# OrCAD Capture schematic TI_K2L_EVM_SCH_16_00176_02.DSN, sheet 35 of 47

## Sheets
35 PAGE43 : K2L_POWER SECTION 2: size C; title: Top Avatar, 12v to CVVD , 12v to 1.5v, 3.3v aux -> 1.2v, 3.3v aux -> 1.8v
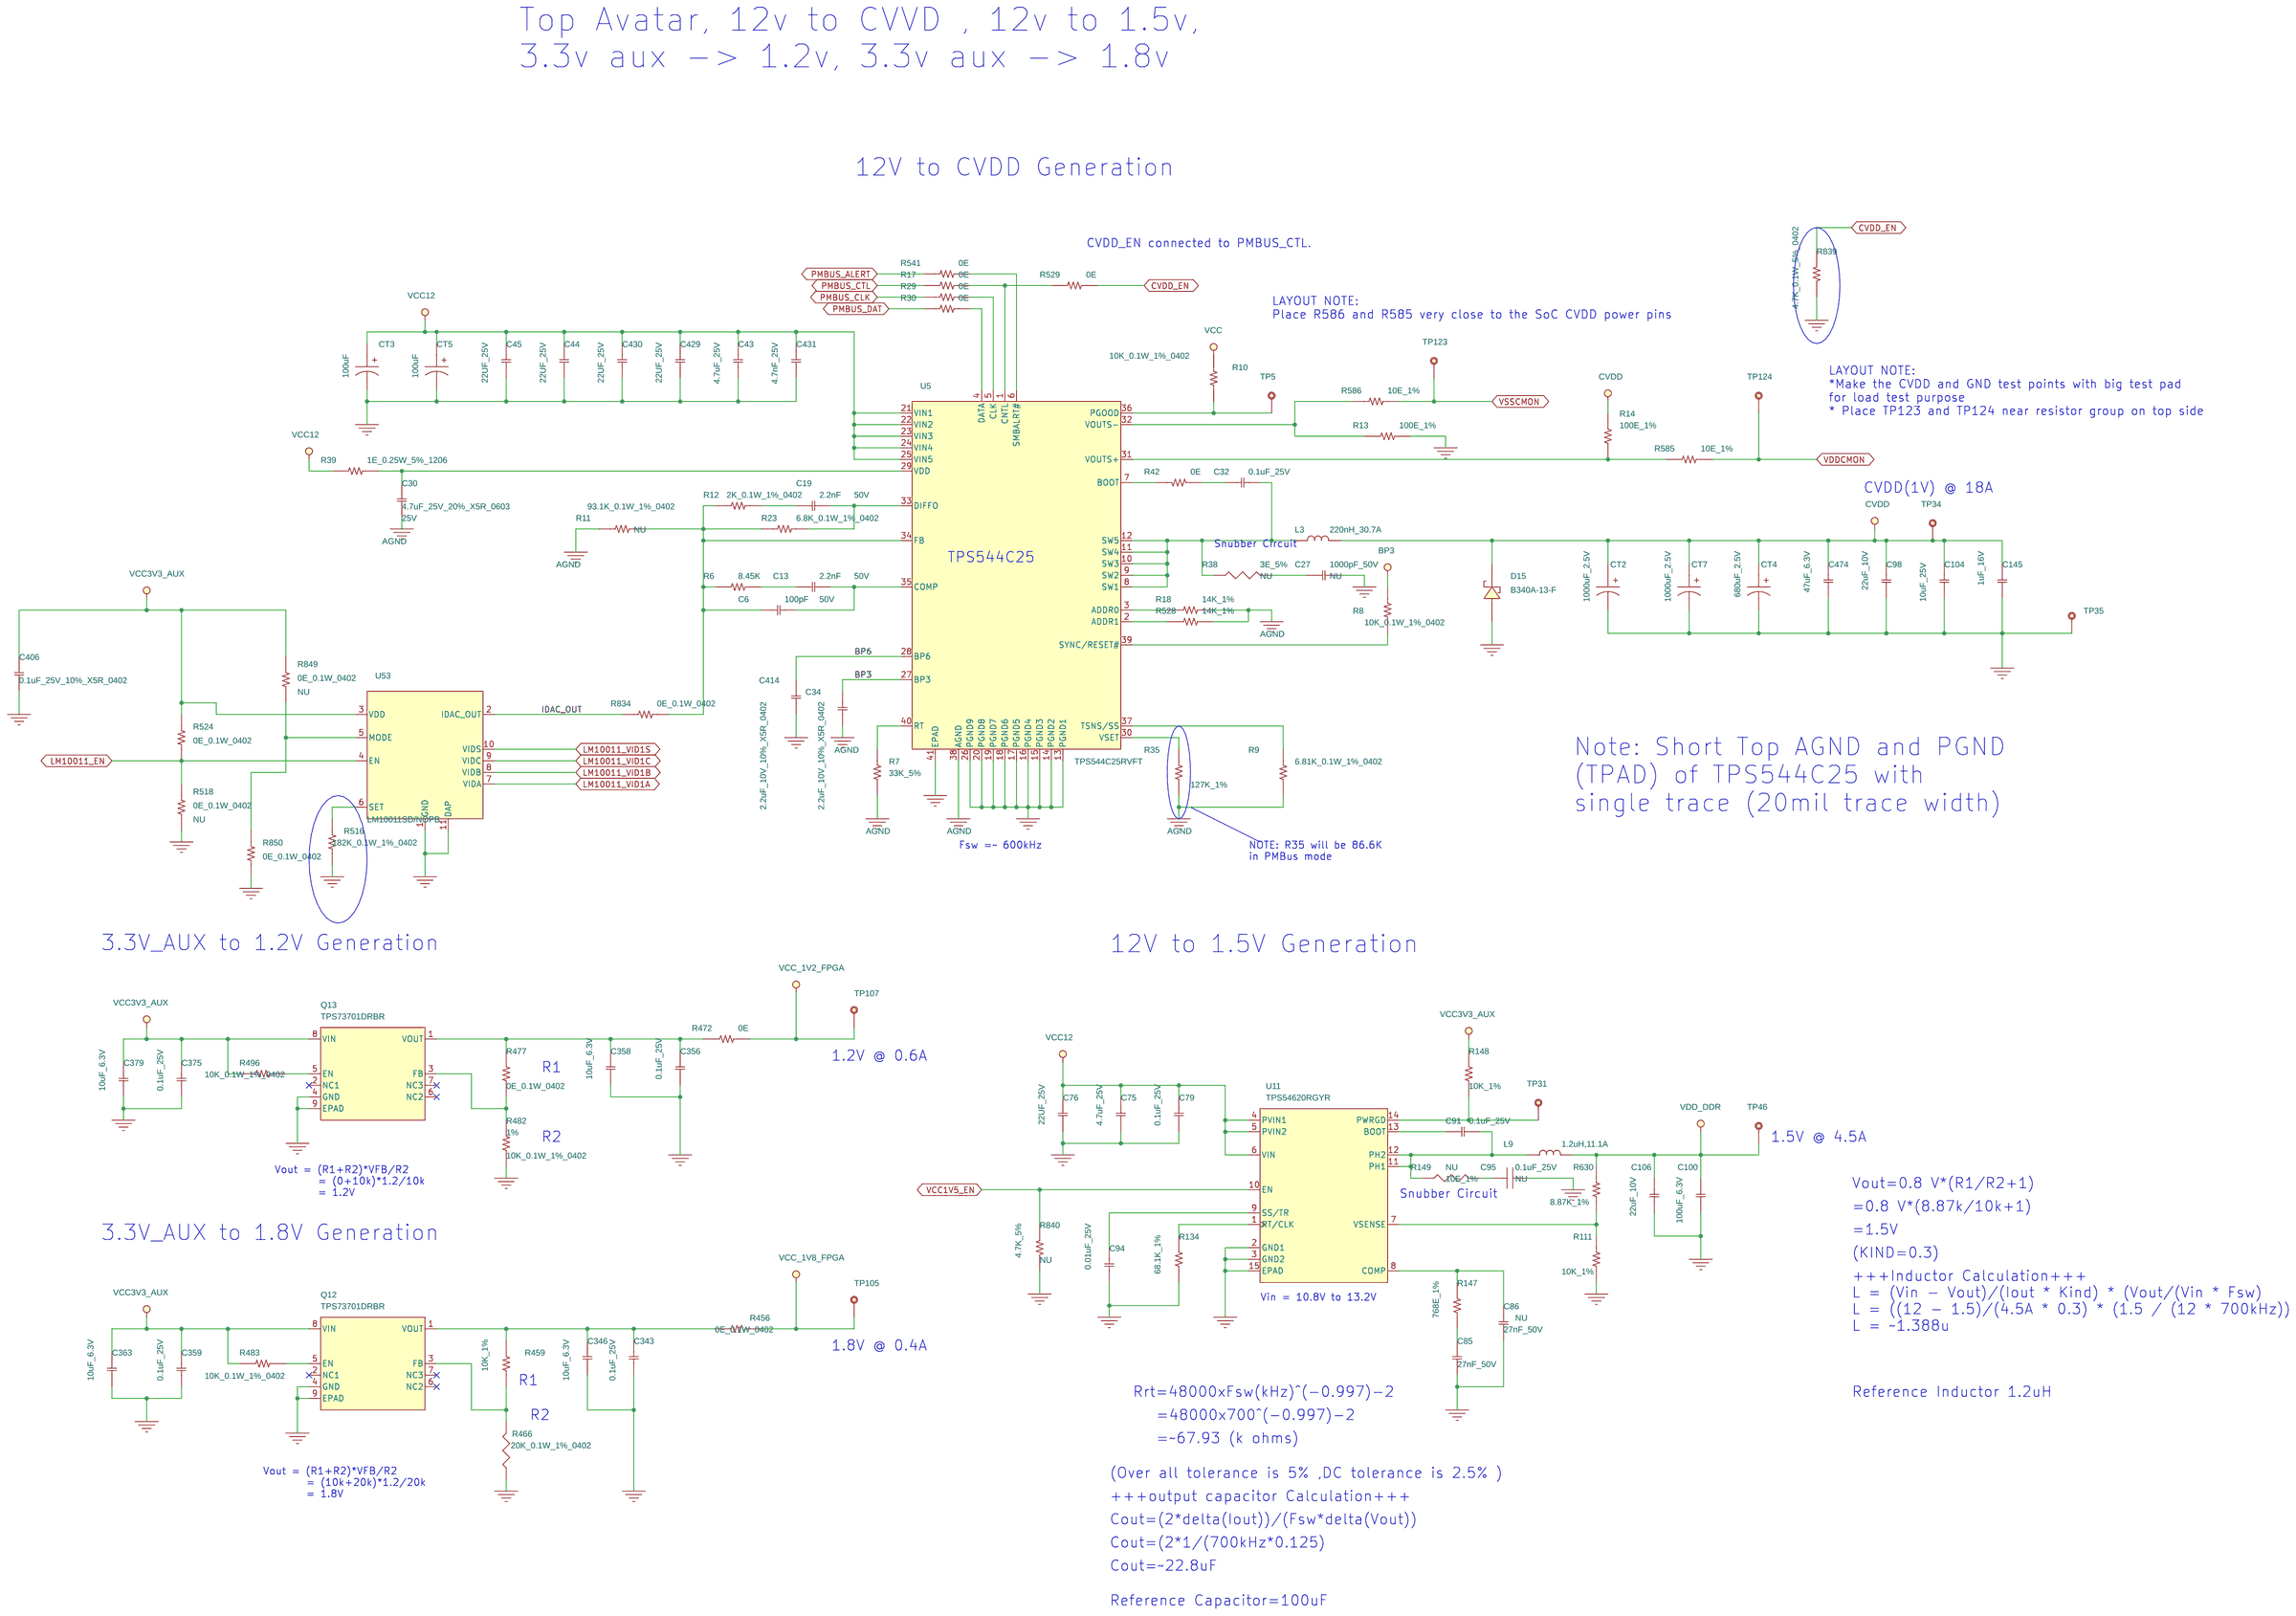
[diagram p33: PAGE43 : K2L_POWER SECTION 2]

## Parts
C6  100pF  [C0402]
C13  2.2nF  [C0402]
C19  2.2nF  [C0402]
C27  1000pF_50V  [C0402]
C30  4.7uF_25V_20%_X5R_0603  [C0603]
C32  0.1uF_25V  [C0402]
C34  2.2uF_10V_10%_X5R_0402  [C0402]
C43  4.7uF_25V  [C0603]
C44  22UF_25V  [C0805]
C45  22UF_25V  [C0805]
C75  4.7uF_25V  [C0603]
C76  22UF_25V  [C0805]
C79  0.1uF_25V  [C0402]
C85  27nF_50V  [C0805]
C86  27nF_50V  [C0805]
C91  0.1uF_25V  [C0402]
C94  0.01uF_25V  [C0402]
C95  0.1uF_25V  [C0402]
C98  22uF_10V  [C0805]
C100  100uF_6.3V  [C1206-1]
C104  10uF_25V  [C0603]
C106  22uF_10V  [C0805]
C145  1uF_16V  [C0402]
C343  0.1uF_25V  [C0402]
C346  10uF_6.3V  [C0603]
C356  0.1uF_25V  [C0402]
C358  10uF_6.3V  [C0603]
C359  0.1uF_25V  [C0402]
C363  10uF_6.3V  [C0603]
C375  0.1uF_25V  [C0402]
C379  10uF_6.3V  [C0603]
C406  0.1uF_25V_10%_X5R_0402  [C0402]
C414  2.2uF_10V_10%_X5R_0402  [C0402]
C429  22UF_25V  [C0805]
C430  22UF_25V  [C0805]
C431  4.7nF_25V  [CC0402]
C474  47uF_6.3V  [C0805]
CT2  1000uF_2.5V  [CT7343]
CT3  100uF  [CT7343]
CT4  680uF_2.5V  [CT7343]
CT5  100uF  [CT7343]
CT7  1000uF_2.5V  [CT7343]
D15  B340A-13-F  [DIODE_2P_158_197X110]
L3  220nH_30.7A  [IND_IHLP3232DZERR47M01]
L9  1.2uH,11.1A  [IND_XAL5030-222MEB]
Q12  TPS73701DRBR  [QFN_8P_26_118x118]
Q13  TPS73701DRBR  [QFN_8P_26_118x118]
R6  8.45K  [R0402]
R7  33K_5%  [R0402]
R8  10K_0.1W_1%_0402  [R0402]
R9  6.81K_0.1W_1%_0402  [R0402]
R10  10K_0.1W_1%_0402  [R0402]
R11  93.1K_0.1W_1%_0402  [R0402]
R12  2K_0.1W_1%_0402  [R0402]
R13  100E_1%  [R0402]
R14  100E_1%  [R0402]
R17  0E  [R0402]
R18  14K_1%  [R0402]
R23  6.8K_0.1W_1%_0402  [R0402]
R29  0E  [R0402]
R30  0E  [R0402]
R35  127K_1%  [R0402]
R38  3E_5%  [R0805]
R39  1E_0.25W_5%_1206  [R1206]
R42  0E  [R0402]
R111  10K_1%  [R0402]
R134  68.1K_1%  [R0603]
R147  768E_1%  [R0603]
R148  10K_1%  [R0402]
R149  10E_1%  [R0402]
R456  0E_0.1W_0402  [R0402]
R459  10K_1%  [R0402]
R466  20K_0.1W_1%_0402  [RC0402]
R472  0E  [R0402]
R477  0E_0.1W_0402  [R0402]
R482  10K_0.1W_1%_0402  [R0402]
R483  10K_0.1W_1%_0402  [R0402]
R496  10K_0.1W_1%_0402  [R0402]
R516  182K_0.1W_1%_0402  [R0402]
R518  0E_0.1W_0402  [R0402]
R524  0E_0.1W_0402  [R0402]
R528  14K_1%  [R0402]
R529  0E  [R0402]
R541  0E  [R0402]
R585  10E_1%  [R0402]
R586  10E_1%  [R0402]
R630  8.87K_1%  [R0402]
R834  0E_0.1W_0402  [R0402]
R839  4.7K_0.1W_5%_0402  [R0402]
R840  4.7K_5%  [R0402]
R849  0E_0.1W_0402  [R0402]
R850  0E_0.1W_0402  [R0402]
TP5  TP  [TP-S40]
TP31  TP  [TP-S40]
TP34  TP  [TP_71C]
TP35  TP  [TP_71C]
TP46  TP  [TP-S40]
TP105  TP  [TP-S40]
TP107  TP  [TP-S40]
TP123  TP  [TP-S40]
TP124  TP  [TP-S40]
U5  TPS544C25RVFT  [QFN50P500X700X152-41N]
U11  TPS54620RGYR  [QFN_14P_20_138x138_TP79]
U53  LM10011SD/NOPB  [WSON50P300X300X80-11N]

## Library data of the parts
C6 = Cap_Ceramic: CAP CER 100PF 50V 5% NP0 0402; Characteristic: <Characteristic>; Distributor_name: DIGIKEY; Distributor_part_number: 490-5922-1-ND; EIC Part#: 03_00594_01; Manufacture: Murata; Manufacture Part Number: GRM1555C1H101JA01D; Manufacture(English): 490-5922-1-ND; Manufacture_Part_Number: GRM1555C1H101JA01D; Manufacturer: Murata; Manufacturer_Part_No: GRM1555C1H101JA01D; Mfg: Murata; Mfg Part#: GRM1555C1H101JA01D; Mfr_name: Murata; Mfr_part_number: GRM1555C1H101JA01D; Oper. Temp. Range: -55°C ~ 125°C; Package: 0402; Price @ 1: 0.10000; Price @ 10K: 0.00500; Price @ 1K: 0.00600; ProcessType: SMT; RoHS: Yes; Tolerance: 5%; Vendor: DIGIKEY; Vendor Part#: 490-5922-1-ND; Vendor_Part_No: 490-5922-1-ND; Voltage: 50V; eI Part#: 03_00594_01
C13 C19 = Cap_Ceramic: CAP CER 2200PF 50V 10% X7R 0402; Distributor_name: Digikey; Distributor_part_number: 445-1257-1-ND; EIC Part#: TBD; Manufacture: TDK Corporation; Manufacture Part Number: C1005X7R1H222K050BA; Manufacture(English): TDK Corporation; Manufacture_Part_Number: C1005X7R1H222K050BA; Manufacturer: TDK Corporation; Manufacturer_Part_No: C1005X7R1H222K050BA; Mfg: TDK Corporation; Mfg Part#: C1005X7R1H222K050BA; Mfr_name: TDK Corporation; Mfr_part_number: C1005X7R1H222K050BA; Oper. Temp. Range: -55C to 85C; Package: 0402; ProcessType: SMT; RoHS: Yes; Tolerance: 10%; Vendor: DigiKey; Vendor Part#: 445-1257-6-ND; Voltage: 50V; eI Part#: TBD
C27 = 11_C_0: CAP CER 1000PF 50V 10% X7R 0402; Advansus_Part_Number: 11G232110214030; Distributor_name: DIGIKEY; Distributor_part_number: 1276-1493-1-ND; EIC Part#: 03_00591_01; Manufacture: Samsung; Manufacture Part Number: CL05B102KB5NFNC; Manufacture(English): Samsung; Manufacture_Part_Number: CL05B102KB5NFNC; Manufacturer: Samsung; Manufacturer_Part_No: CL05B102KB5NFNC; Mfg: Samsung; Mfg Part#: CL05B102KB5NFNC; Mfr_name: Samsung; Mfr_part_number: CL05B102KB5NFNC; Mounting: NU; Mounting Status: NU; Mounting_Status: NU; Oper. Temp. Range: -55C to 85C; Package: 0402; Price @ 1: 0.10000; Price @ 10K: 0.00260; Price @ 1K: 0.00372; ProcessType: SMT; RoHS: Yes; Tolerance: 10%; Vendor: DIGIKEY; Vendor Part#: 1276-1493-1-ND; Vendor_Part_No: 1276-1493-1-ND; Voltage: 50V; eI Part#: 03_00591_01
C30 C43 C75 = 11_C_0: CAP CER 4.7UF 25V 20% X5R 0603; Distributor_name: DIGIKEY; Distributor_part_number: 1276-1903-2-ND; EIC Part#: 03_00592_01; Manufacture: Samsung; Manufacture Part Number: CL10A475MA8NQNC; Manufacture(English): Samsung; Manufacture_Part_Number: CL10A475MA8NQNC; Manufacturer: Samsung; Manufacturer_Part_No: CL10A475MA8NQNC; Mfg: Samsung; Mfg Part#: CL10A475MA8NQNC; Mfr_name: Samsung; Mfr_part_number: CL10A475MA8NQNC; Oper. Temp. Range: -55C to 85C; Package: 0603; ProcessType: SMT; RoHS: Yes; Tolerance: 10%; Vendor: DIGIKEY; Vendor Part#: 1276-1903-2-ND; Vendor_Part_No: 1276-1903-2-ND; Voltage: 25V; eI Part#: 03_00592_01
C32 C79 C91 C406 = 11_C_0: CAP CER 0.1UF 25V 10% X5R 0402; Alt Mfg: Taiyo Yuden; Distributor_name: DIGIKEY; Distributor_part_number: 445-4964-1-ND; EIC Part#: 03_00470_02; Manufacture: TDK Corporation; Manufacture Part Number: C1005X5R1E104K050BC; Manufacture(English): TDK Corporation; Manufacture_Part_Number: GRM155R61E104KA87D; Manufacturer: TDK Corporation; Manufacturer_Part_No: C1005X5R1E104K050BC; Mfg: Murata Electronics North America; Mfg Part#: 03_00470_02; Mfr_name: TDK Corporation; Mfr_part_number: C1005X5R1E104K050BC; Oper. Temp. Range: -55°C ~ 85°C; Package: 0402; Price @ 1: 0.10000; Price @ 1K: 0.00960; ProcessType: SMT; RoHS: Yes; Tolerance: 10%; Vendor: DIGIKEY; Vendor Part#: 445-4964-1-ND; Vendor_Part_No: 445-4964-1-ND; eI Part#: 03_00470_02
C34 C414 = 11_C_12: CAP CER 2.2UF 10V 10% X5R 0402; Characteristic: <Characteristic>; Distributor_name: DIGIKEY; Distributor_part_number: 445-7392-1-ND; EIC Part#: 03_00055_05; Manufacture: TDK Corporation; Manufacture Part Number: C1005X5R1A225K050BC; Manufacture(English): TDK Corporation; Manufacture_Part_Number: C1005X5R1A225K050BC; Manufacturer: TDK Corporation; Manufacturer_Part_No: C1005X5R1A225K050BC; Mfg: TDK Corporation; Mfg Part#: C1005X5R1A225K050BC; Mfr_name: TDK Corporation; Mfr_part_number: C1005X5R1A225K050BC; Oper. Temp. Range: -55C to 105C; Package: 0402; Price @ 1: 0.32000; Price @ 10K: 0.06400; Price @ 1K: 0.09200; ProcessType: SMT; RoHS: Yes; Specifications: CAP CER 2.2UF 10V 10% X5R 0402; Tolerance: 10%; Vendor: DIGIKEY; Vendor Part#: 445-7392-1-ND; Vendor_Part_No: 445-7392-1-ND; Voltage: 6.3V; eI Part#: 03_00055_05
C44 C45 C76 C429 C430 = 11_C_0: CAP CER 22UF 25V 20% JB 0805; Alternate_Mfr: Samsung; Alternate_Partno: CL21A226MAQNNNE; Distributor_name: DIGIKEY; Distributor_part_number: 445-11475-2-ND; EIC Part#: 03_00586_01; Manufacture: TDK Corporation; Manufacture Part Number: C2012JB1E226M125AC; Manufacture(English): TDK Corporation; Manufacture_Part_Number: C2012JB1E226M125AC; Manufacturer: TDK Corporation; Manufacturer_Part_No: C2012JB1E226M125AC; Mfg: TDK Corporation; Mfg Part#: C2012JB1E226M125AC; Mfr_name: TDK Corporation; Mfr_part_number: C2012JB1E226M125AC; Oper. Temp. Range: -55C to 85C; Package: 0805; Price @ 1: 1.09000; Price @ 10K: 0.26265; Price @ 1K: 0.37647; ProcessType: SMT; RoHS: Yes; Tolerance: 10%; Vendor: DIGIKEY; Vendor Part#: 490-5527-1-ND; Vendor_Part_No: 03_00586_01; Voltage: 25V; eI Part#: 03_00586_01
C85 = 11_C_0: CAP CER 0.027UF 50V 10% X7R 0805; Distributor_name: DIGIKEY; Distributor_part_number: 311-1139-1-ND; EIC Part#: 03_00588_01; Manufacture: Yageo; Manufacture Part Number: CC0805KRX7R9BB273; Manufacture(English): Yageo; Manufacture_Part_Number: CC0805KRX7R9BB273; Manufacturer: Yageo; Manufacturer_Part_No: CC0805KRX7R9BB273; Mfg: Yageo; Mfg Part#: 03_00588_01; Mfr_name: Yageo; Mfr_part_number: CC0805KRX7R9BB273; Oper. Temp. Range: -55C ~ 125C; Package: 0805; Price @ 1: 0.10000; Price @ 10K: 0.01320; Price @ 1K: 0.01722; ProcessType: SMT; RoHS: Yes; Tolerance: 10%; Vendor: DIGIKEY; Vendor Part#: 311-1139-1-ND; Vendor_Part_No: 311-1139-1-ND; Voltage: 50V; eI Part#: 03_00588_01
C86 = 11_C_0: CAP CER 0.027UF 50V 10% X7R 0805; Distributor_name: DIGIKEY; Distributor_part_number: 311-1139-1-ND; EIC Part#: 03_00588_01; Manufacture: Yageo; Manufacture Part Number: CC0805KRX7R9BB273; Manufacture(English): Yageo; Manufacture_Part_Number: CC0805KRX7R9BB273; Manufacturer: Yageo; Manufacturer_Part_No: CC0805KRX7R9BB273; Mfg: Yageo; Mfg Part#: 03_00588_01; Mfr_name: Yageo; Mfr_part_number: CC0805KRX7R9BB273; Mounting: NU; Mounting Status: NU; Mounting_Status: NU; Oper. Temp. Range: -55C ~ 125C; Package: 0805; Price @ 1: 0.10000; Price @ 10K: 0.01320; Price @ 1K: 0.01722; ProcessType: SMT; RoHS: Yes; Tolerance: 10%; Vendor: DIGIKEY; Vendor Part#: 311-1139-1-ND; Vendor_Part_No: 311-1139-1-ND; Voltage: 50V; eI Part#: 03_00588_01
C94 = 11_C_0: CAP CER 10000PF 25V 10% X7R 0402; Alt Mfg: Murata; Alt Mfg Part#: GRM155R71C103KA01D; Distributor_name: DIGIKEY; Distributor_part_number: 445-1260-1-ND; EIC Part#: 03_00029_04; Manufacture: TDK Corporation; Manufacture Part Number: C1005X7R1E103K; Manufacture(English): TDK Corporation; Manufacture_Part_Number: C1005X7R1E103K; Manufacturer: TDK Corporation; Manufacturer_Part_No: C1005X7R1E103K; Mfg: TDK Corporation; Mfg Part#: 03_00029_04; Mfr_name: TDK Corporation; Mfr_part_number: C1005X7R1E103K; Oper. Temp. Range: -55C to 125C; Package: 0402; Price @ 1: 0.10000; Price @ 10K: 0.00420; Price @ 1K: 0.00600; ProcessType: SMT; RoHS: Yes; Tolerance: 10%; Vendor: DIGIKEY; Vendor Part#: PCC103BQCT-ND; Vendor_Part_No: 445-1260-1-ND; Voltage: 16V; eI Part#: 03_00029_04
C95 = CAP_NP: CAP CER 0.1UF 25V 10% X5R 0402; Alt Mfg: Taiyo Yuden; Distributor_name: DIGIKEY; Distributor_part_number: 445-4964-1-ND; EIC Part#: 03_00470_02; Manufacture: TDK Corporation; Manufacture Part Number: C1005X5R1E104K050BC; Manufacture(English): TDK Corporation; Manufacture_Part_Number: GRM155R61E104KA87D; Manufacturer: TDK Corporation; Manufacturer_Part_No: C1005X5R1E104K050BC; Mfg: Murata Electronics North America; Mfg Part#: 03_00470_02; Mfr_name: TDK Corporation; Mfr_part_number: C1005X5R1E104K050BC; Mounting: NU; Mounting Status: NU; Mounting_Status: NU; Oper. Temp. Range: -55°C ~ 85°C; Package: 0402; Price @ 1: 0.10000; Price @ 1K: 0.00960; RoHS: Yes; Vendor: DIGIKEY; Vendor Part#: 445-4964-1-ND; Vendor_Part_No: 445-4964-1-ND; eI Part#: 03_00470_02
C98 = Cap_Ceramic: CAP CER 22UF 10V 20% X5R 0805; Characteristic: <Characteristic>; Distributor_name: DIGIKEY; Distributor_part_number: 587-1958-1-ND; EIC Part#: 03_00263_01; Manufacture: Taiyo Yuden; Manufacture Part Number: LMK212BJ226MG-T; Manufacture(English): Taiyo Yuden; Manufacture_Part_Number: LMK212BJ226MG-T; Manufacturer: Taiyo Yuden; Manufacturer_Part_No: LMK212BJ226MG-T; Mfg: Taiyo Yuden; Mfg Part#: 03_00263_01; Mfr_name: Taiyo Yuden; Mfr_part_number: LMK212BJ226MG-T; Oper. Temp. Range: -55C to 85C; Package: 0805; Price @ 1: 0.53000; Price @ 10K: 0.12000; Price @ 1K: 0.16875; ProcessType: SMT; RoHS: Yes; Tolerance: 20%; Vendor: DIGIKEY; Vendor Part#: 587-1958-1-ND; Vendor_Part_No: 587-1958-1-ND; eI Part#: 03_00263_01
C100 = 11_C_0: CAP CER 100UF 6.3V 20% X5R 1206; Distributor_name: DIGIKEY; Distributor_part_number: 587-1453-1-ND; EIC Part#: 03_00380_04; Manufacture: Taiyo Yuden; Manufacture Part Number: JMK316BJ107ML-T; Manufacture(English): Taiyo Yuden; Manufacture_Part_Number: JMK316BJ107ML-T; Manufacturer: Taiyo Yuden; Manufacturer_Part_No: JMK316BJ107ML-T; Mfg: Taiyo Yuden; Mfg Part#: 03_00380_04; Mfr_name: Taiyo Yuden; Mfr_part_number: JMK316BJ107ML-T; Oper. Temp. Range: -55C to 85C; Package: 1206; Price @ 1: 1.80000; Price @ 10K: 0.30450; Price @ 1K: 0.43050; ProcessType: SMT; RoHS: Yes; Tolerance: 20%; Vendor: DIGIKEY; Vendor Part#: 587-1963-1-ND; Vendor_Part_No: 587-1453-1-ND; Voltage: 6.3V; eI Part#: 03_00380_04
C104 = Cap_Ceramic: CAP CER 10UF 25V 20% X5R 0603; Characteristic: <Characteristic>; Distributor_name: DIGIKEY; Distributor_part_number: 445-9015-1-ND; EIC Part#: 03_00609_01; Manufacture: TDK Corporation; Manufacture Part Number: C1608X5R1E106M080AC; Manufacture(English): TDK Corporation; Manufacture_Part_Number: C1608X5R1E106M080AC; Manufacturer: TDK Corporation; Manufacturer_Part_No: C1608X5R1E106M080AC; Mfg: TDK Corporation; Mfg Part#: C1608X5R1E106M080AC; Mfr_name: TDK Corporation; Mfr_part_number: C1608X5R1E106M080AC; Oper. Temp. Range: -55C to 85C; Package: 0603; ProcessType: SMT; RoHS: Yes; Tolerance: 20%; Vendor: DIGIKEY; Vendor Part#: TDK Corporation; Vendor_Part_No: 445-9015-1-ND; eI Part#: 03_00609_01
C106 = 11_C_0: CAP CER 22UF 10V 20% X5R 0805; Distributor_name: DIGIKEY; Distributor_part_number: 587-1958-1-ND; EIC Part#: 03_00263_01; Manufacture: Taiyo Yuden; Manufacture Part Number: LMK212BJ226MG-T; Manufacture(English): Taiyo Yuden; Manufacture_Part_Number: LMK212BJ226MG-T; Manufacturer: Taiyo Yuden; Manufacturer_Part_No: LMK212BJ226MG-T; Mfg: Taiyo Yuden; Mfg Part#: 03_00263_01; Mfr_name: Taiyo Yuden; Mfr_part_number: LMK212BJ226MG-T; Oper. Temp. Range: -55C to 85C; Package: 0805; Price @ 1: 0.53000; Price @ 10K: 0.12000; Price @ 1K: 0.16875; ProcessType: SMT; RoHS: Yes; Tolerance: 20%; Vendor: DIGIKEY; Vendor Part#: 587-1958-1-ND; Vendor_Part_No: 587-1958-1-ND; Voltage: 10V; eI Part#: 03_00263_01
C145 = Cap_Ceramic: CAP CER 1UF 16V 10% X5R 0402; Characteristic: <Characteristic>; Distributor_name: DIGIKEY; Distributor_part_number: 445-4978-1-ND; EIC Part#: 03_00355_04; Manufacture: TDK Corporation; Manufacture Part Number: C1005X5R1C105K050BC; Manufacture(English): TDK Corporation; Manufacture_Part_Number: C1005X5R1C105K050BC; Manufacturer: TDK Corporation; Manufacturer_Part_No: C1005X5R1C105K050BC; Mfg: TDK Corporation; Mfg Part#: C1005X5R1C105K050BC; Mfr_name: TDK Corporation; Mfr_part_number: C1005X5R1C105K050BC; Oper. Temp. Range: -55C to 85C; Package: 0402; ProcessType: SMT; RoHS: Yes; Tolerance: 10%; Vendor: DIGIKEY; Vendor Part#: 445-4978-1-ND; Vendor_Part_No: 445-4978-1-ND; eI Part#: 03_00355_04
C343 C356 C359 C375 = 11_C_0: CAP CER 0.1UF 25V 10% X5R 0402; Alt Mfg: Murata; Distributor_name: DIGIKEY; Distributor_part_number: 445-4964-1-ND; EIC Part#: 03_00470_02; Manufacture: TDK Corporation; Manufacture Part Number: C1005X5R1E104K050BC; Manufacture(English): TDK Corporation; Manufacture_Part_Number: GRM155R61E104KA87D; Manufacturer: TDK Corporation; Manufacturer_Part_No: C1005X5R1E104K050BC; Mfg: Murata Electronics North America; Mfg Part#: 03_00470_02; Mfr_name: TDK Corporation; Mfr_part_number: C1005X5R1E104K050BC; Oper. Temp. Range: -55C to 85C; Package: 0402; Price @ 1: 0.10000; Price @ 1K: 0.00960; ProcessType: SMT; RoHS: Yes; Tolerance: 10%; Vendor: DIGIKEY; Vendor Part#: 445-4964-1-ND; Vendor_Part_No: 445-4964-1-ND; eI Part#: 03_00470_02
C346 C358 C363 C379 = 11_C_0: CAP CER 10UF 6.3V 20% X5R 0603; Distributor_name: DIGIKEY; Distributor_part_number: 587-3383-1-ND; EIC Part#: 03_00605_01; Manufacture: Taiyo Yuden; Manufacture Part Number: JMK107ABJ106MAHT; Manufacture(English): Taiyo Yuden; Manufacture_Part_Number: JMK107ABJ106MAHT; Manufacturer: Taiyo Yuden; Manufacturer_Part_No: JMK107ABJ106MAHT; Mfg: Taiyo Yuden; Mfg Part#: JMK107ABJ106MAHT; Mfr_name: Taiyo Yuden; Mfr_part_number: JMK107ABJ106MAHT; Oper. Temp. Range: -55C to 85C; Package: 0603; Price @ 10K: 0.06105; ProcessType: SMT; RoHS: Yes; Tolerance: 20%; Vendor: DIGIKEY; Vendor Part#: 587-3383-1-ND; Vendor_Part_No: 587-3383-1-ND; eI Part#: 03_00605_01
C431 = 11_C_0: CAP CER 4700PF 25V 10% X7R 0402; Distributor_name: DIGIKEY; Distributor_part_number: 311-1039-1-ND; EIC Part#: 03_00338_03; Manufacture: Yageo; Manufacture Part Number: CC0402KRX7R8BB472; Manufacture(English): Yageo; Manufacture_Part_Number: CC0402KRX7R8BB472; Manufacturer: Yageo; Manufacturer_Part_No: CC0402KRX7R8BB472; Mfg: Yageo; Mfg Part#: 03_00338_03; Mfr_name: Yageo; Mfr_part_number: CC0402KRX7R8BB472; Oper. Temp. Range: -55C to 85C; Package: 0402; Price @ 1: 0.10000; Price @ 10K: 0.00216; Price @ 1K: 0.00309; ProcessType: SMT; RoHS: Yes; Tolerance: 10%; Vendor: DIGIKEY; Vendor Part#: 311-1039-1-ND; Vendor_Part_No: 311-1039-1-ND; Voltage: 25V; eI Part#: 03_00338_03
C474 = Cap_Ceramic: CAP CER 47UF 6.3V 20% X5R 0805; Distributor_name: DIGIKEY; Distributor_part_number: 587-1779-1-ND; EIC Part#: 03_00328_01; Manufacture: Taiyo Yuden; Manufacture Part Number: JMK212BJ476MG-T; Manufacture(English): Taiyo Yuden; Manufacturer: Taiyo Yuden; Manufacturer_Part_No: JMK212BJ476MG-T; Mfg: Taiyo Yuden; Mfg Part#: 03_00328_01; Mfr_name: Taiyo Yuden; Mfr_part_number: JMK212BJ476MG-T; Oper. Temp. Range: -55C to 105C; Package: 0805; ProcessType: SMT; RoHS: Yes; Tolerance: 20%; Vendor: DIGIKEY; Vendor Part#: 587-1779-1-ND; Vendor_Part_No: 587-1779-1-ND; eI Part#: 03_00328_01
CT2 CT7 = CAP_POL: CAP TANT 1000UF 2.5V 20% 2917; Distributor_name: DIGIKEY; Distributor_part_number: 399-4749-1-ND; EIC Part#: 03_00287_01; Manufacture: Kemet; Manufacture Part Number: T530Y108M2R5ATE005; Manufacture(English): Kemet; Manufacturer: Kemet; Manufacturer_Part_No: T530Y108M2R5ATE005; Mfg: Kemet; Mfg Part#: 03_00287_01; Mfr_name: Kemet; Mfr_part_number: T530Y108M2R5ATE005; Oper. Temp. Range: -55°C ~ 105°C; Package: 7343; RoHS: Yes; Vendor: DIGIKEY; Vendor Part#: 399-4749-2-ND; Vendor_Part_No: 399-4749-1-ND; eI Part#: 03_00287_01
CT3 CT5 = CAP_POL: CAP TANT 100UF 20V 10% 2917; Distributor_name: DIGIKEY; Distributor_part_number: 718-1774-1-ND; EIC Part#: 03_00602_01; Manufacture: Vishay; Manufacture Part Number: TR3D107K020C0080; Manufacture(English): Vishay Dale; Manufacture_Part_Number: TR3D107K020C0080; Manufacturer: Vishay Dale; Manufacturer_Part_No: TR3D107K020C0080; Mfg: Vishay Dale; Mfg Part#: TR3D107K020C0080; Mfr_name: Vishay Dale; Mfr_part_number: TR3D107K020C0080; Oper. Temp. Range: -40°C ~ 85°C; Package: 7343; RoHS: Yes; Vendor: DIGIKEY; Vendor Part#: 718-1774-1-ND; Vendor_Part_No: 718-1774-1-ND; Voltage: 25V; eI Part#: 03_00602_01
CT4 = CAP_POL: CAP TANT 680UF 2.5V 20% 2917; Distributor_name: DIGIKEY; Distributor_part_number: P16221CT-ND; EIC Part#: TBD; Manufacture: Panasonic - ECG; Manufacture Part Number: 2R5TPF680ML; Manufacture(English): Panasonic - ECG; Manufacturer: Panasonic - ECG; Manufacturer_Part_No: 2R5TPF680ML; Mfg: Panasonic - ECG; Mfg Part#: TBD; Mfr_name: Panasonic - ECG; Mfr_part_number: 2R5TPF680ML; Oper. Temp. Range: -55°C ~ 105°C; Package: 7343; RoHS: Yes; Vendor: DIGIKEY; Vendor Part#: P16221CT-ND; Vendor_Part_No: P16221CT-ND; eI Part#: TBD
D15 = Schottky_Diode: DIODE SCHOTTKY 3A 40V SMA; Distributor_name: DIGIKEY; Distributor_part_number: B340A-FDICT-ND; EIC Part#: 06_00002_01; Manufacture: Diodes Inc; Manufacture(English): Diodes Inc; Manufacturer: Diodes Inc; Mfg: Diodes Inc; Mfr_name: Diodes Inc; Oper. Temp. Range: -55C to 85C; Package: DO-214AC; RoHS: Yes; Vendor: DigiKey; Vendor Part#: B340A-FDICT-ND; Vendor_Part_No: B340A-FDICT-ND; eI Part#: 06_00002_01
L3 = 1211_CHOKE_0: INDUCTOR POWER .22UH 30.7A SMD; Distributor_name: DIGIKEY; Distributor_part_number: 541-1378-1-ND; EIC Part#: TBD; Manufacture: Vishay Dale; Manufacture Part Number: IHLP3232DZERR22M01; Manufacture(English): Vishay Dale; Manufacturer: Vishay Dale; Manufacturer_Part_No: IHLP3232DZERR22M01; Mfg: Coilcraft; Mfg Part#: TBD; Mfr_name: Vishay Dale; Mfr_part_number: IHLP3232DZERR22M01; ProcessType: SMT; RoHS: Yes; Vendor: DIGIKEY; Vendor Part#: 541-1378-1-ND; Vendor_Part_No: 541-1378-1-ND; eI Part#: TBD
L9 = 1211_CHOKE_0: INDUCTOR 1.2UH  20% SMD; Current: 2.3A Irms; Distributor_name: Mouser; Distributor_part_number: 994-XAL5030-122MEB; EIC Part#: 04_00410_01; Manufacture: Coilcraft Inc; Manufacture Part Number: XAL5030-122MEB; Manufacture(English): Coilcraft Inc; Manufacture_Part_Number: XAL5030-122MEB; Manufacturer: Coilcraft Inc; Manufacturer_Part_No: XAL5030-122MEB; Mfg Part#: 04_00410_01; Mfr_name: Coilcraft Inc; Mfr_part_number: XAL5030-122MEB; ProcessType: SMT; RoHS: Yes; Tolerance: 20%; Vendor: Mouser; Vendor Part#: XAL5030-122MEB; Vendor_Part_No: 994-XAL5030-122MEB; eI Part#: 04_00410_01
Q12 Q13 = TPS73701DRBT: IC REG LDO ADJ 1A 8SON; Distributor_name: DIGIKEY; Distributor_part_number: 296-22065-1-ND; EIC Part#: 01_00822_01; Manufacture: TI; Manufacture(English): TI; Manufacturer: TI; Mfg: TI; Mfg Part#: 01_00822_01; Mfr_name: TI; Oper. Temp. Range: -40°C ~ 125°C; Package: SON8; Price @ 1: 1.72000; Price @ 10K: 0.67500; Price @ 1K: 0.68851; ProcessType: SMT; RoHS: Yes; Vendor: DIGIKEY; Vendor Part#: 296-27067-1-ND; Vendor_Part_No: 296-22065-1-ND; eI Part#: 01_00822_01
R6 = 10_R_0: RES 8.45K OHM 1/16W 1% 0402 SMD; Distributor_name: Digikey; Distributor_part_number: 541-8.45KLCT-ND; EIC Part#: TBD; Manufacture: Vishay Dale; Manufacture Part Number: CRCW04028K45FKED; Manufacture(English): Vishay Dale; Manufacture_Part_Number: CRCW04028K45FKED; Manufacturer: Vishay Dale; Manufacturer_Part_No: CRCW04028K45FKED; Mfg: Vishay Dale; Mfg Part#: CRCW04028K45FKED; Mfr_name: Vishay Dale; Mfr_part_number: CRCW04028K45FKED; Oper. Temp. Range: -55C ~ 125C; Package: 0402; ProcessType: SMT; Remark: Alt part is 1/16W; RoHS: Yes; Tolerance: 1%; Vendor: DigiKey; Vendor Part#: 541-8.45KLCT-ND; eI Part#: TBD
R7 = 10_R_0: RES 33K OHM 1/10W 5% 0402 SMD; Distributor_name: DIGIKEY; Distributor_part_number: P33KJCT-ND; EIC Part#: 02_00356_01; Manufacture: Panasonic - ECG; Manufacture Part Number: ERJ-2GEJ333X; Manufacture(English): Panasonic - ECG; Manufacture_Part_Number: ERJ-2GEJ333X; Manufacturer: Panasonic - ECG; Manufacturer_Part_No: ERJ-2GEJ333X; Mfg Part#: 02_00356_01; Mfr_name: Panasonic - ECG; Mfr_part_number: ERJ-2GEJ333X; Oper. Temp. Range: -55C ~ 125C; Package: 0402; ProcessType: SMT; Remark: Alt part is 1/10W; RoHS: Yes; Tolerance: 5%; Vendor: DIGIKEY; Vendor Part#: P33KJCT-ND; Vendor_Part_No: P33KJCT-ND; eI Part#: 02_00483_01
R8 R10 R111 R148 R459 R482 R483 R496 = 10_R_0: RES 10K OHM 1/10W 1% 0402 SMD; Alt Mfg: Yageo; Alt Mfg Part#: RC0402FR-0710KL; Distributor_name: DIGIKEY; Distributor_part_number: P10.0KLCT-ND; EIC Part#: 02_00027_01; Manufacture: Panasonic - ECG; Manufacture Part Number: ERJ-2RKF1002X; Manufacture(English): Panasonic - ECG; Manufacture_Part_Number: ERJ-2RKF1002X; Manufacturer: Panasonic - ECG; Manufacturer_Part_No: ERJ-2RKF1002X; Mfg Part#: 02_00027_01; Mfr_name: Panasonic - ECG; Mfr_part_number: ERJ-2RKF1002X; Oper. Temp. Range: -55C ~ 125C; Package: 0402; Price @ 1: 0.10000; Price @ 10K: 0.00347; Price @ 1K: 0.00672; ProcessType: SMT; Remark: Alt part is 1/16W; RoHS: Yes; Tolerance: 1%; Vendor: DIGIKEY; Vendor Part#: P10.0KLCT-ND; Vendor_Part_No: P10.0KLCT-ND; eI Part#: 02_00027_01
R9 = 10_R_0: RES 6.81K OHM 1/10W 1% 0402 SMD; Alt Mfg: Yageo; Alt Mfg Part#: RC0402FR-0710KL; Distributor_name: DIGIKEY; Distributor_part_number: P6.81KLCT-ND; EIC Part#: 02_00414_01; Manufacture: Panasonic - ECG; Manufacture Part Number: ERJ-2RKF6811X; Manufacture(English): Panasonic - ECG; Manufacture_Part_Number: ERJ-2RKF6811X; Manufacturer: Panasonic - ECG; Manufacturer_Part_No: ERJ-2RKF6811X; Mfg Part#: 02_00414_01; Mfr_name: Panasonic - ECG; Mfr_part_number: ERJ-2RKF6811X; Oper. Temp. Range: -55C ~ 125C; Package: 0402; ProcessType: SMT; Remark: Alt part is 1/10W; RoHS: Yes; Tolerance: 1%; Vendor: DIGIKEY; Vendor Part#: P6.81KLCT-ND; Vendor_Part_No: P6.81KLCT-ND; eI Part#: 02_00720_01
R11 = 10_R_0: RES 93.1K OHM 1/10W 1% 0402 SMD; Alt Mfg: Yageo; Alt Mfg Part#: RC0402FR-0710KL; Distributor_name: DIGIKEY; Distributor_part_number: P93.1KLCT-ND; EIC Part#: 02_00316_01; Manufacture: Panasonic - ECG; Manufacture Part Number: ERJ-2RKF9312X; Manufacture(English): Panasonic - ECG; Manufacture_Part_Number: ERJ-2RKF9312X; Manufacturer: Panasonic - ECG; Manufacturer_Part_No: ERJ-2RKF9312X; Mfg Part#: 02_00316_01; Mfr_name: Panasonic - ECG; Mfr_part_number: ERJ-2RKF9312X; Mounting: NU; Mounting Status: NU; Mounting_Status: NU; Oper. Temp. Range: -55C ~ 125C; Package: 0402; ProcessType: SMT; Remark: Alt part is 1/10W; RoHS: Yes; Tolerance: 1%; Vendor: DIGIKEY; Vendor Part#: P93.1KLCT-ND; Vendor_Part_No: P93.1KLCT-ND; eI Part#: 02_00356_01
R12 = 10_R_0: RES 2K OHM 1/10W 1% 0402 SMD; Characteristic: 1%; Distributor_name: DIGIKEY; Distributor_part_number: P2.00KLCT-ND; EIC Part#: 02_00229_02; Manufacture: Panasonic - ECG; Manufacture Part Number: ERJ-2RKF2001X; Manufacture(English): Panasonic - ECG; Manufacture_Part_Number: ERJ-2RKF2001X; Manufacturer: Panasonic - ECG; Manufacturer_Part_No: ERJ-2RKF2001X; Mfg: Panasonic - ECG; Mfg Part#: ERJ-2RKF2001X; Mfr_name: Panasonic - ECG; Mfr_part_number: ERJ-2RKF2001X; Oper. Temp. Range: -55C to 125C; Package: 0402; Price @ 1: 0.10000; ProcessType: SMT; RoHS: Yes; Tolerance: 1%; Vendor: DIGIKEY; Vendor Part#: P2.00KLCT-ND; Vendor_Part_No: P2.00KLCT-ND; eI Part#: 02_00229_02
R13 = 10_R_0: RES 100 OHM 1/10W 1% 0402 SMD; Distributor_name: DIGIKEY; Distributor_part_number: P100LCT-ND; EIC Part#: 02_00043_02; Manufacture: Panasonic - ECG; Manufacture Part Number: ERJ-2RKF1000X; Manufacture(English): Panasonic - ECG; Manufacture_Part_Number: ERJ-2RKF1000X; Manufacturer: Panasonic - ECG; Manufacturer_Part_No: ERJ-2RKF1000X; Mfg Part#: 02_00043_02; Mfr_name: Panasonic - ECG; Mfr_part_number: ERJ-2RKF1000X; Oper. Temp. Range: -55C to 125C; Package: 0402; ProcessType: SMT; RoHS: Yes; Tolerance: 1%; Vendor: DIGIKEY; Vendor Part#: P100LCT-ND; Vendor_Part_No: P100LCT-ND; eI Part#: 02_00019_01
R14 = 10_R_0: RES 100 OHM 1/10W 1% 0402 SMD; Distributor_name: DIGIKEY; Distributor_part_number: P100LCT-ND; EIC Part#: 02_00043_02; Manufacture: Panasonic - ECG; Manufacture Part Number: ERJ-2RKF1000X; Manufacture(English): Panasonic - ECG; Manufacture_Part_Number: ERJ-2RKF1000X; Manufacturer: Panasonic - ECG; Manufacturer_Part_No: ERJ-2RKF1000X; Mfg Part#: 02_00043_02; Mfr_name: Panasonic - ECG; Mfr_part_number: ERJ-2RKF1000X; Oper. Temp. Range: -55C to 125C; Package: 0402; ProcessType: SMT; RoHS: Yes; Tolerance: 1%; Vendor: DIGIKEY; Vendor Part#: P100LCT-ND; Vendor_Part_No: P100LCT-ND; eI Part#: NA
R17 R29 R30 R42 R456 R472 R477 R524 R529 R541 R834 R850 = 10_R_0: RES 0.0 OHM 1/10W JUMP 0402 SMD; Alt Mfg: Yageo; Distributor_name: DIGIKEY; Distributor_part_number: P0.0JCT-ND; EIC Part#: 02_00019_01; Manufacture: Panasonic - ECG; Manufacture Part Number: ERJ-2GE0R00X; Manufacture(English): Panasonic - ECG; Manufacture_Part_Number: ERJ-2GE0R00X; Manufacturer: Panasonic - ECG; Manufacturer_Part_No: ERJ-2GE0R00X; Mfg Part#: 02_00019_01; Mfr_name: Panasonic - ECG; Mfr_part_number: ERJ-2GE0R00X; Oper. Temp. Range: -55C to 125C; Package: 0402; ProcessType: SMT; Remark: Alt part is 1/16W; RoHS: Yes; Tolerance: 5%; Vendor: DIGIKEY; Vendor Part#: P0.0JCT-ND; Vendor_Part_No: P0.0JCT-ND; eI Part#: 02_00019_01
R18 R528 = 10_R_0: RES 14K OHM 1/10W 1% 0402 SMD; Distributor_name: DIGIKEY; Distributor_part_number: TBD; EIC Part#: TBD; Manufacture: Panasonic - ECG; Manufacture Part Number: ERJ-2RKF1402X; Manufacture(English): Panasonic - ECG; Manufacture_Part_Number: ERJ-2RKF1402X; Manufacturer: Panasonic - ECG; Manufacturer_Part_No: ERJ-2RKF1402X; Mfg Part#: TBD; Mfr_name: Panasonic - ECG; Mfr_part_number: ERJ-2RKF1402X; Oper. Temp. Range: -55C ~ 125C; Package: 0402; ProcessType: SMT; Remark: Alt part is 1/10W; RoHS: Yes; Tolerance: 1%; Vendor: DIGIKEY; Vendor Part#: TBD; Vendor_Part_No: TBD; eI Part#: TBD
R23 = 10_R_0: RES 6.80K OHM 1/16W 1% 0402 SMD; Distributor_name: Digikey; Distributor_part_number: TBD; EIC Part#: TBD; Manufacture: Yageo; Manufacture Part Number: RC0402FR-076K8L; Manufacture(English): Yageo; Manufacture_Part_Number: RC0402FR-076K8L; Manufacturer: Yageo; Manufacturer_Part_No: RC0402FR-076K8L; Mfg: Yageo; Mfg Part#: RC0402FR-076K8L; Mfr_name: Yageo; Mfr_part_number: RC0402FR-076K8L; Oper. Temp. Range: -55C to 125C; Package: 0402; ProcessType: SMT; Remark: Alt part is 1/16W; RoHS: Yes; Tolerance: 1%; Vendor: DIGIKEY; Vendor Part#: TBD; Vendor_Part_No: TBD; eI Part#: TBD
R35 = 10_R_0: RES 127K OHM 1/10W 1% 0402 SMD; Distributor_name: DIGIKEY; Distributor_part_number: TBD; EIC Part#: TBD; Manufacture: Panasonic - ECG; Manufacture Part Number: ERJ-2RKF1273X; Manufacture(English): Panasonic - ECG; Manufacture_Part_Number: ERJ-2RKF1273X; Manufacturer: Panasonic - ECG; Manufacturer_Part_No: ERJ-2RKF1273X; Mfg: Panasonic - ECG; Mfg Part#: ERJ-2RKF1273X; Mfr_name: Panasonic - ECG; Mfr_part_number: ERJ-2RKF1273X; Oper. Temp. Range: -55C ~ 125C; Package: 0402; ProcessType: SMT; Remark: Alt part is 1/16W; RoHS: Yes; Tolerance: 1%; Vendor: DIGIKEY; Vendor Part#: TBD; Vendor_Part_No: TBD; eI Part#: TBD
R38 = RESISTOR: RES 3 OHM 1/8W 5% 0805 SMD; Distributor_name: DIGIKEY; Distributor_part_number: P3.0ACT-ND; EIC Part#: TBD; Manufacture: Panasonic - ECG; Manufacture Part Number: ERJ-6GEYJ3R0V; Manufacture(English): Panasonic - ECG; Manufacture_Part_Number: ERJ-6GEYJ3R0V; Manufacturer: Panasonic - ECG; Manufacturer_Part_No: ERJ-6GEYJ3R0V; Mfg Part#: TBD; Mfr_name: Panasonic - ECG; Mfr_part_number: ERJ-6GEYJ3R0V; Mounting: NU; Mounting Status: NU; Mounting_Status: NU; Oper. Temp. Range: -55C to 125C; Package: 0805; RoHS: Yes; Specifications: RES 3 OHM 1/8W 5% 0805 SMD; Tolerance: 5%; Vendor: DIGIKEY; Vendor Part#: P3.0ACT-ND; Vendor_Part_No: P3.0ACT-ND; eI Part#: 02_00297_02
R39 = 10_R_0: RES 1 OHM 1/4W 5% 1206 SMD; Alt Mfg: Yageo; Alt Mfg Part#: RC0402FR-0710KL; Distributor_name: DIGIKEY; Distributor_part_number: P1.0ECT-ND; EIC Part#: 02_00971_01; Manufacture: Panasonic - ECG; Manufacture Part Number: ERJ-8GEYJ1R0V; Manufacture(English): Panasonic - ECG; Manufacture_Part_Number: ERJ-8GEYJ1R0V; Manufacturer: Panasonic - ECG; Manufacturer_Part_No: ERJ-8GEYJ1R0V; Mfg Part#: 02_00971_01; Mfr_name: Panasonic - ECG; Mfr_part_number: ERJ-8GEYJ1R0V; Oper. Temp. Range: -55C ~ 125C; Package: 1206; ProcessType: SMT; Remark: 0.25W, 1/4W; RoHS: Yes; Tolerance: 1%; Vendor: DIGIKEY; Vendor Part#: P1.0ECT-ND; Vendor_Part_No: P1.0ECT-ND; eI Part#: 02_00024_01
R134 = 10_R_0: RES 68.1K OHM 1/10W 1% 0603 SMD; Distributor_name: DIGIKEY; Distributor_part_number: P68.1KHCT-ND; EIC Part#: 02_00969_01; Manufacture: Panasonic - ECG; Manufacture Part Number: ERJ-3EKF6812V; Manufacture(English): Panasonic - ECG; Manufacture_Part_Number: ERJ-3EKF6812V; Manufacturer: Panasonic - ECG; Manufacturer_Part_No: ERJ-3EKF6812V; Mfg Part#: 02_00969_01; Mfr_name: Panasonic - ECG; Mfr_part_number: ERJ-3EKF6812V; Oper. Temp. Range: -55C ~ 125C; Package: 0603; ProcessType: SMT; RoHS: Yes; Tolerance: 1%; Vendor: DIGIKEY; Vendor Part#: P68.1KHCT-ND; Vendor_Part_No: P68.1KHCT-ND; eI Part#: 02_00019_01
R147 = 10_R_0: RES 768 OHM 1/10W 1% 0603 SMD; Distributor_name: DIGIKEY; Distributor_part_number: P768HCT-ND; EIC Part#: 02_00970_01; Manufacture: Panasonic - ECG; Manufacture Part Number: ERJ-3EKF7680V; Manufacture(English): Panasonic - ECG; Manufacture_Part_Number: ERJ-3EKF7680V; Manufacturer: Panasonic - ECG; Manufacturer_Part_No: ERJ-3EKF7680V; Mfg Part#: 02_00970_01; Mfr_name: Panasonic - ECG; Mfr_part_number: ERJ-3EKF7680V; Oper. Temp. Range: -55C ~ 125C; Package: 0603; ProcessType: SMT; RoHS: Yes; Tolerance: 1%; Vendor: DIGIKEY; Vendor Part#: P768HCT-ND; Vendor_Part_No: P768HCT-ND; eI Part#: 02_00297_02
R149 = RESISTOR: RES 10.0 OHM 1/10W 1% 0402 SMD; Alt Mfg: Yageo; Alt Mfg Part#: RC0402FR-0710RL; Distributor_name: DIGIKEY; Distributor_part_number: P10.0LCT-ND; EIC Part#: 02_00348_01; Manufacture: Panasonic - ECG; Manufacture Part Number: ERJ-2RKF10R0X; Manufacture(English): Panasonic - ECG; Manufacture_Part_Number: ERJ-2RKF10R0X; Manufacturer: Panasonic - ECG; Manufacturer_Part_No: ERJ-2RKF10R0X; Mfg: Panasonic Electronic Components; Mfg Part#: 02_00348_01; Mfr_name: Panasonic - ECG; Mfr_part_number: ERJ-2RKF10R0X; Mounting: NU; Mounting Status: NU; Mounting_Status: NU; Oper. Temp. Range: -55C to 125C; Package: 0402; Price @ 1: 0.10000; Price @ 10K: 0.00347; Price @ 1K: 0.00672; RoHS: Yes; Specifications: RES 10.0 OHM 1/10W 1% 0402 SMD; Tolerance: 1%; Vendor: DIGIKEY; Vendor Part#: P10.0LCT-ND; Vendor_Part_No: P10.0LCT-ND; eI Part#: 02_00269_01
R466 = DISC_RESISTOR: RES 20.0K OHM 1/10W 1% 0402 SMD; Distributor_name: DIGIKEY; Distributor_part_number: P20.0KLCT-ND; EIC Part#: 02_00037_01; Manufacture: Panasonic - ECG; Manufacture Part Number: ERJ-2RKF2002X; Manufacture(English): Panasonic - ECG; Manufacture_Part_Number: ERJ-2RKF2002X; Manufacturer: Panasonic - ECG; Manufacturer_Part_No: ERJ-2RKF2002X; Mfg Part#: 02_00037_01; Mfr_name: Panasonic - ECG; Mfr_part_number: ERJ-2RKF2002X; Price @ 1: 0.10000; Price @ 10K: 0.00347; Price @ 1K: 0.00672; RoHS Compliant?: RoHS Compliant; Vendor: DIGIKEY; Vendor_Part_No: P20.0KLCT-ND; eI Part#: 02_00027_01
R516 = 10_R_0: RES 182K OHM 1/10W 1% 0402 SMD; Distributor_name: DIGIKEY; Distributor_part_number: P182KLCT-ND; EIC Part#: TBD; Manufacture: Panasonic - ECG; Manufacture Part Number: ERJ-2RKF1823X; Manufacture(English): Panasonic - ECG; Manufacture_Part_Number: ERJ-2RKF1823X; Manufacturer: Panasonic - ECG; Manufacturer_Part_No: ERJ-2RKF1823X; Mfg Part#: ERJ-2RKF1823X; Mfr_name: Panasonic - ECG; Mfr_part_number: ERJ-2RKF1823X; Oper. Temp. Range: -55C to 125C; Package: 0402; ProcessType: SMT; Remark: Alt part is 1/16W; RoHS: Yes; Tolerance: 1%; Vendor: DIGIKEY; Vendor Part#: P182KLCT-ND; Vendor_Part_No: P182KLCT-ND; eI Part#: TBD
R518 R849 = 10_R_0: RES 0.0 OHM 1/10W JUMP 0402 SMD; Alt Mfg: Yageo; Distributor_name: DIGIKEY; Distributor_part_number: P0.0JCT-ND; EIC Part#: 02_00019_01; Manufacture: Panasonic - ECG; Manufacture Part Number: ERJ-2GE0R00X; Manufacture(English): Panasonic - ECG; Manufacture_Part_Number: ERJ-2GE0R00X; Manufacturer: Panasonic - ECG; Manufacturer_Part_No: ERJ-2GE0R00X; Mfg Part#: 02_00019_01; Mfr_name: Panasonic - ECG; Mfr_part_number: ERJ-2GE0R00X; Mounting: NU; Mounting Status: NU; Mounting_Status: NU; Oper. Temp. Range: -55C to 125C; Package: 0402; ProcessType: SMT; Remark: Alt part is 1/16W; RoHS: Yes; Tolerance: 5%; Vendor: DIGIKEY; Vendor Part#: P0.0JCT-ND; Vendor_Part_No: P0.0JCT-ND; eI Part#: 02_00019_01
R585 R586 = 10_R_0: RES 10.0 OHM 1/10W 1% 0402 SMD; Characteristic: 5%; Distributor_name: DIGIKEY; Distributor_part_number: P10.0LCT-ND; EIC Part#: 02_00348_01; Manufacture: Panasonic - ECG; Manufacture Part Number: ERJ-2RKF10R0X; Manufacture(English): Panasonic - ECG; Manufacture_Part_Number: ERJ-2RKF10R0X; Manufacturer: Panasonic - ECG; Manufacturer_Part_No: ERJ-2RKF10R0X; Mfg: Panasonic Electronic Components; Mfg Part#: 02_00348_01; Mfr_name: Panasonic - ECG; Mfr_part_number: ERJ-2RKF10R0X; Oper. Temp. Range: -55C to 125C; Package: 0402; Price @ 1: 0.10000; Price @ 10K: 0.00347; Price @ 1K: 0.00672; ProcessType: SMT; RoHS: Yes; Tolerance: 1%; Vendor: DIGIKEY; Vendor Part#: P10.0LCT-ND; Vendor_Part_No: P10.0LCT-ND; eI Part#: 02_00348_01
R630 = 10_R_0: RES 8.87K OHM 1/10W 1% 0402 SMD; Distributor_name: DIGIKEY; Distributor_part_number: P8.87KLCT-ND; EIC Part#: 02_00966_01; Manufacture: Panasonic - ECG; Manufacture Part Number: ERJ-2RKF8871X; Manufacture(English): Panasonic - ECG; Manufacture_Part_Number: ERJ-2RKF8871X; Manufacturer: Panasonic - ECG; Manufacturer_Part_No: ERJ-2RKF8871X; Mfg: Panasonic - ECG; Mfg Part#: ERJ-2RKF8871X; Mfr_name: Panasonic - ECG; Mfr_part_number: ERJ-2RKF8871X; Oper. Temp. Range: -55C ~ 125C; Package: 0402; ProcessType: SMT; RoHS: Yes; Tolerance: 1%; Vendor: DIGIKEY; Vendor Part#: P8.87KLCT-ND; Vendor_Part_No: P8.87KLCT-ND; eI Part#: 02_00966_01
R839 = 10_R_0: RES 4.7K OHM 1/10W 5% 0402 SMD; Distributor_name: DIGIKEY; Distributor_part_number: P4.7KJCT-ND; EIC Part#: 02_00023_01; Manufacture: Panasonic - ECG; Manufacture Part Number: ERJ-2GEJ472X; Manufacture(English): Panasonic - ECG; Manufacture_Part_Number: ERJ-2GEJ472X; Manufacturer: Panasonic - ECG; Manufacturer_Part_No: ERJ-2GEJ472X; Mfg: Panasonic Electronic Components; Mfg Part#: 02_00266_01; Mfr_name: Panasonic - ECG; Mfr_part_number: ERJ-2GEJ472X; Price @ 1: 0.10000; Price @ 10K: 0.00347; Price @ 1K: 0.00672; Vendor: DIGIKEY; Vendor_Part_No: P4.7KJCT-ND; eI Part#: 02_00023_01
R840 = 10_R_0: RES 4.7K OHM 1/10W 5% 0402 SMD; Distributor_name: DIGIKEY; Distributor_part_number: P4.7KJCT-ND; EIC Part#: 02_00023_01; Manufacture: Panasonic - ECG; Manufacture Part Number: ERJ-2GEJ472X; Manufacture(English): Panasonic - ECG; Manufacture_Part_Number: ERJ-2GEJ472X; Manufacturer: Panasonic - ECG; Manufacturer_Part_No: ERJ-2GEJ472X; Mfg: Panasonic Electronic Components; Mfg Part#: 02_00266_01; Mfr_name: Panasonic - ECG; Mfr_part_number: ERJ-2GEJ472X; Mounting Status: NU; Mounting_Status: NU; Price @ 1: 0.10000; Price @ 10K: 0.00347; Price @ 1K: 0.00672; Vendor: DIGIKEY; Vendor_Part_No: P4.7KJCT-ND; eI Part#: 02_00023_01
TP5 TP31 TP46 TP105 TP107 TP123 TP124 = 00_TP-S40_0: TEST PAD TP; Distributor_name: NA; Distributor_part_number: NA; EIC Part#: NA; Manufacture: NA; Manufacture Part Number: NA; Manufacture(English): NA; Manufacture_Part_Number: NA; Manufacturer: NA; Manufacturer_Part_No: NA; Mfg: NA; Mfg Part#: NA; Mfr_name: NA; Mfr_part_number: NA; Oper. Temp. Range: --NA--; Package: --NA--; Price @ 1: NA; Price @ 10K: NA; Price @ 1K: NA; ProcessType: SMT; RoHS: Yes; Vendor: NA; Vendor Part#: --NA--; Vendor_Part_No: NA; eI Part#: NA
TP34 TP35 = 00_TP-S40_0: TEST PAD TP; Distributor_name: NA; Distributor_part_number: NA; EIC Part#: NA; Manufacture: NA; Manufacture Part Number: NA; Manufacture(English): NA; Manufacture_Part_Number: NA; Manufacturer: NA; Manufacturer_Part_No: NA; Mfg: NA; Mfg Part#: NA; Mfr_name: NA; Mfr_part_number: NA; Oper. Temp. Range: --NA--; Package: --NA--; Price @ 1: NA; Price @ 10K: NA; Price @ 1K: NA; ProcessType: SMT; RoHS: Yes; Vendor: NA; Vendor Part#: --NA--; Vendor_Part_No: NA; eI Part#: 01_00391_01
U5 = TPS544B20: 18V 30A PMBUS SYNCHRONOUS BUCK CONVERTER; Distributor_name: TBD; Distributor_part_number: TBD; EIC Part#: TBD; Manufacture: TI; Manufacture Part Number: TPS544C24RVFT; Manufacture(English): TI; Manufacture_Part_Number: TPS544C24RVFT; Manufacturer: TI; Manufacturer_Part_No: TPS544C24RVFT; Mfg: TI; Mfg Part#: TBD; Mfr_name: TI; Mfr_part_number: TPS544C24RVFT; Price @ 1: TBD; Price @ 10K: TBD; Price @ 1K: TBD; Vendor: TBD; Vendor_Part_No: TBD; eI Part#: TBD
U11 = TPS54620RGY: IC REG BUCK SYNC ADJ 6A 14VQFN; Distributor_name: DIGIKEY; Distributor_part_number: 296-24554-1-ND; EIC Part#: 01_00391_01; Manufacture: TI; Manufacture(English): TI; Manufacturer: TI; Mfg: TI; Mfg Part#: 01_00391_01; Mfr_name: TI; Oper. Temp. Range: -40°C ~ 150°C; Package: QFN14; Price @ 1: 6.48000; Price @ 10K: 2.81250; Price @ 1K: 2.86875; ProcessType: SMT; RoHS: Yes; Vendor: DIGIKEY; Vendor Part#: 296-24554-1-ND; Vendor_Part_No: 296-24554-1-ND; eI Part#: 01_00391_01
U53 = LM10011SD: IC VID VOLTAGE PROGRAMMER 10SON; Distributor_name: DIGIKEY; Distributor_part_number: 296-35633-1-ND; EIC Part#: 01_01133_01; Manufacture: TI; Manufacture(English): TI; Manufacturer: TI; Mfg: TI; Mfg Part#: 01_01133_01; Mfr_name: TI; Price @ 1: 1.72000; Price @ 10K: 0.67500; Price @ 1K: 0.67500; Vendor: DIGIKEY; Vendor_Part_No: 296-35633-1-ND; eI Part#: 01_01133_01

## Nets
AGND: C30.2 C34.2 R7.2 R9.2 R11.2 R18.1 R35.1 R528.1 U5.38(AGND)
GND: C27.2 C43.2 C44.2 C45.2 C75.2 C76.2 C79.2 C85.2 C86.2 C94.2 C95.1 C98.2 C100.2 C104.2 C106.2 C145.2 C343.2 C346.2 C356.2 C358.2 C359.2 C363.2 C375.2 C379.2 C406.2 C414.2 C429.2 C430.2 C431.2 C474.2 CT2.2(Negative) CT3.2(Negative) CT4.2(Negative) CT5.2(Negative) CT7.2(Negative) D15.1(ANODE) Q12.4(GND) Q12.9(EPAD) Q13.4(GND) Q13.9(EPAD) R13.2 R111.2 R134.1 R466.1 R482.1 R516.1 R518.1 R839.1 R840.1 R850.1 TP35.1 U5.13(PGND1) U5.14(PGND2) U5.15(PGND3) U5.16(PGND4) U5.17(PGND5) U5.18(PGND6) U5.19(PGND7) U5.20(PGND8) U5.26(PGND9) U5.41(EPAD) U11.2(GND1) U11.3(GND2) U11.15(EPAD) U53.1(GND) U53.11(DAP) ; also on sheet 1 2 3 4 5 6 8 10 11 12 13 14 15 16 17 18 19 20 21 22 24 25 26 27 28 29 33 34 36 37 40 41 42 43 45 46 47
VCC1V5_EN: R840.2 U11.10(EN) ; also on sheet 37
VCC3V3_AUX: C359.1 C363.1 C375.1 C379.1 C406.1 Q12.8(VIN) Q13.8(VIN) R148.2 R483.2 R496.2 R524.2 R849.2 U53.3(VDD) ; also on sheet 2 4 6 8 11 12 13 16 18 19 22 25 26 27 28 29 33 37 40 45 47
VCC12: C43.1 C44.1 C45.1 C75.1 C76.1 C79.1 C429.1 C430.1 C431.1 CT3.1(Positive) CT5.1(Positive) R39.2 U5.21(VIN1) U5.22(VIN2) U5.23(VIN3) U5.24(VIN4) U5.25(VIN5) U11.4(PVIN1) U11.5(PVIN2) U11.6(VIN) ; also on sheet 25 33 34
VCC_1V2_FPGA: R472.2 TP107.1 ; also on sheet 29
VCC_1V8_FPGA: R456.2 TP105.1 ; also on sheet 27 28 29
VDD_DDR: C100.1 C106.1 L9.2 R630.1 TP46.1 ; also on sheet 1 19 20 33 37
VDDCMON: R585.1 TP124.1 ; also on sheet 41
VSSCMON: R586.1 TP123.1 ; also on sheet 41
BP3: C34.1 R8.2 R10.1 U5.27(BP3)
BP6: C414.1 U5.28(BP6)
CVDD: C98.1 C104.1 C145.1 C474.1 CT2.1(Positive) CT4.1(Positive) CT7.1(Positive) D15.2(CATHODE) L3.2 R14.2 TP34.1 ; also on sheet 3 36 37
CVDD_EN: R529.2 R839.2 ; also on sheet 37
IDAC_OUT: R834.2 U53.2(IDAC_OUT)
LM10011_EN: R518.2 R524.1 U53.4(EN) ; also on sheet 5
LM10011_VID1A: U53.7(VIDA) ; also on sheet 25
LM10011_VID1B: U53.8(VIDB) ; also on sheet 25
LM10011_VID1C: U53.9(VIDC) ; also on sheet 25 37
LM10011_VID1S: U53.10(VIDS) ; also on sheet 25 37
PMBUS_ALERT: R541.1 ; also on sheet 5 6 34 37
PMBUS_CLK: R29.1 ; also on sheet 34 37
PMBUS_CTL: R17.1 ; also on sheet 5 37
PMBUS_DAT: R30.1 ; also on sheet 34 37
N18337001: C32.2 L3.1 R38.2 U5.8(SW1) U5.9(SW2) U5.10(SW3) U5.11(SW4) U5.12(SW5)
N18337050: R29.2 U5.5(CLK)
N18337052: R30.2 U5.4(DATA)
N18337117: R42.1 U5.7(BOOT)
N18337119: C32.1 R42.2
N18337163: C30.1 R39.1 U5.29(VDD)
N18337220: R7.1 U5.40(RT)
N18337312: R17.2 R529.1 U5.1(CNTL)
N18337316: R541.2 U5.6(SMBALRT#)
N18337544: C6.2 C13.2 U5.35(COMP)
N18337546: C13.1 R6.1
N18337548: C6.1 R6.2 R11.1 R12.2 R23.1 R834.1 U5.34(FB)
N18337560: C19.2 R23.2 U5.33(DIFFO)
N18337562: C19.1 R12.1
N18337572: R516.2 U53.6(SET)
N18337663: C27.1 R38.1
N18337685: R10.2 TP5.1 U5.36(PGOOD)
N18337739: R35.2 U5.30(VSET)
N18337743: R9.1 U5.37(TSNS/SS)
N18337758: R849.1 R850.2 U53.5(MODE)
N18337837: R18.2 U5.3(ADDR0)
N18337839: R528.2 U5.2(ADDR1)
N18367483: R8.1 U5.39(SYNC/RESET#)
N18385140: C94.1 U11.9(SS/TR)
N18385158: R111.1 R630.2 U11.7(VSENSE)
N18385178: C86.1 R147.1 U11.8(COMP)
N18385180: C85.1 R147.2
N18385200: C95.2 R149.1
N18385208: R134.2 U11.1(RT/CLK)
N18385254: R148.1 TP31.1 U11.14(PWRGD)
N18385262: C91.2 L9.1 R149.2 U11.11(PH1) U11.12(PH2)
N18385274: C91.1 U11.13(BOOT)
N19239969: R14.1 R585.2 U5.31(VOUTS+)
N19347858: Q13.3(FB) R477.2 R482.2
N19347862: C356.1 C358.1 Q13.1(VOUT) R472.1 R477.1
N19347872: Q13.5(EN) R496.1
N19349610: Q12.3(FB) R459.2 R466.2
N19349641: C343.1 C346.1 Q12.1(VOUT) R456.1 R459.1
N19349651: Q12.5(EN) R483.1
N19909488: R13.1 R586.2 U5.32(VOUTS-)

Not connected (* = marked no-connect by the designer): Q12 2(NC1)* 6(NC2)* 7(NC3)*; Q13 2(NC1)* 6(NC2)* 7(NC3)*

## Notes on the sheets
sheet 35
- Top Avatar, 12v to CVVD , 12v to 1.5v,
  3.3v aux -> 1.2v, 3.3v aux -> 1.8v
- 12V to CVDD Generation
- CVDD_EN connected to PMBUS_CTL.
- LAYOUT NOTE:
  Place R586 and R585 very close to the SoC CVDD power pins
- LAYOUT NOTE:
  *Make the CVDD and GND test points with big test pad
  for load test purpose
  * Place TP123 and TP124 near resistor group on top side
- CVDD(1V) @ 18A
- Snubber Circuit
- TPS544C25
- Note: Short Top AGND and PGND
  (TPAD) of TPS544C25 with
  single trace (20mil trace width)
- Fsw =~ 600kHz
- NOTE: R35 will be 86.6K
  in PMBus mode
- 3.3V_AUX to 1.2V Generation
- 12V to 1.5V Generation
- 1.2V @ 0.6A
- R1
- R2
- 1.5V @ 4.5A
- Vout = (R1+R2)*VFB/R2
          = (0+10k)*1.2/10k
          = 1.2V
- Snubber Circuit
- Vout=0.8 V*(R1/R2+1)
- =0.8 V*(8.87k/10k+1)
- 3.3V_AUX to 1.8V Generation
- =1.5V
- (KIND=0.3)
- +++Inductor Calculation+++
  L = (Vin - Vout)/(Iout * Kind) * (Vout/(Vin * Fsw)
  L = ((12 - 1.5)/(4.5A * 0.3) * (1.5 / (12 * 700kHz))
  L = ~1.388u
- Vin = 10.8V to 13.2V
- 1.8V @ 0.4A
- R1
- Rrt=48000xFsw(kHz)^(-0.997)-2
- Reference Inductor 1.2uH
- R2
- =48000x700^(-0.997)-2
- =~67.93 (k ohms)
- Vout = (R1+R2)*VFB/R2
          = (10k+20k)*1.2/20k
          = 1.8V
- (Over all tolerance is 5% ,DC tolerance is 2.5% )
- +++output capacitor Calculation+++
- Cout=(2*delta(Iout))/(Fsw*delta(Vout))
- Cout=(2*1/(700kHz*0.125)
- Cout=~22.8uF
- Reference Capacitor=100uF
